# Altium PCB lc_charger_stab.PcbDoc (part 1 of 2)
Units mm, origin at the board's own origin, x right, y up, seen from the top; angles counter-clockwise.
Board outline 145 x 80 mm, 2 copper layers (Top Layer, Bottom Layer), stack 1.562 mm thick; 160 components, 79 nets, 423 pads, 71 vias.
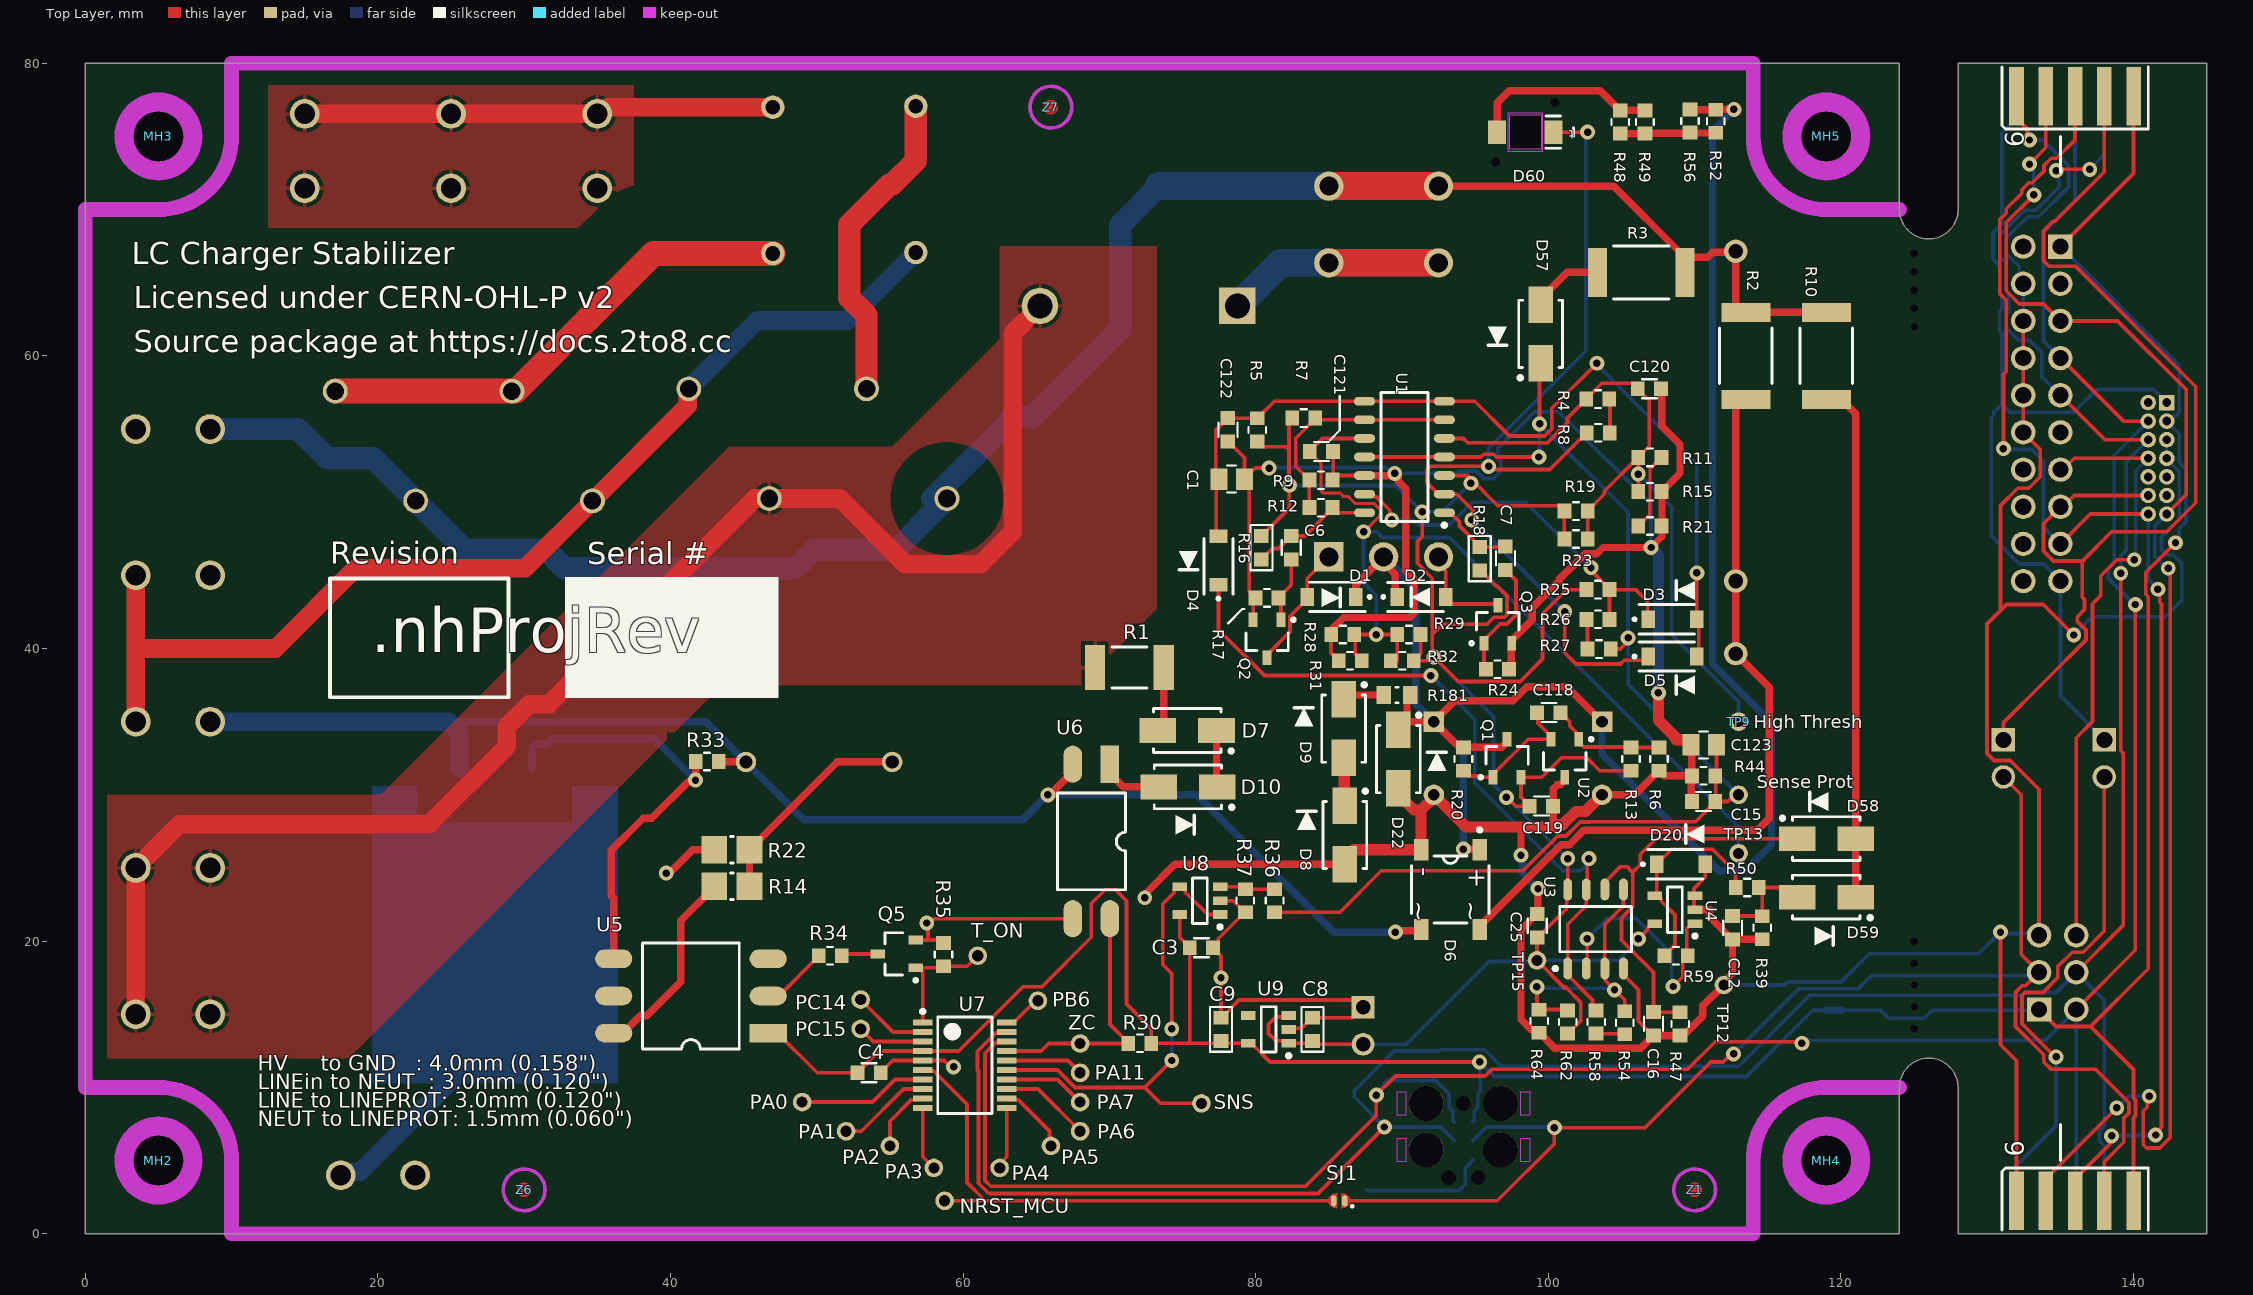
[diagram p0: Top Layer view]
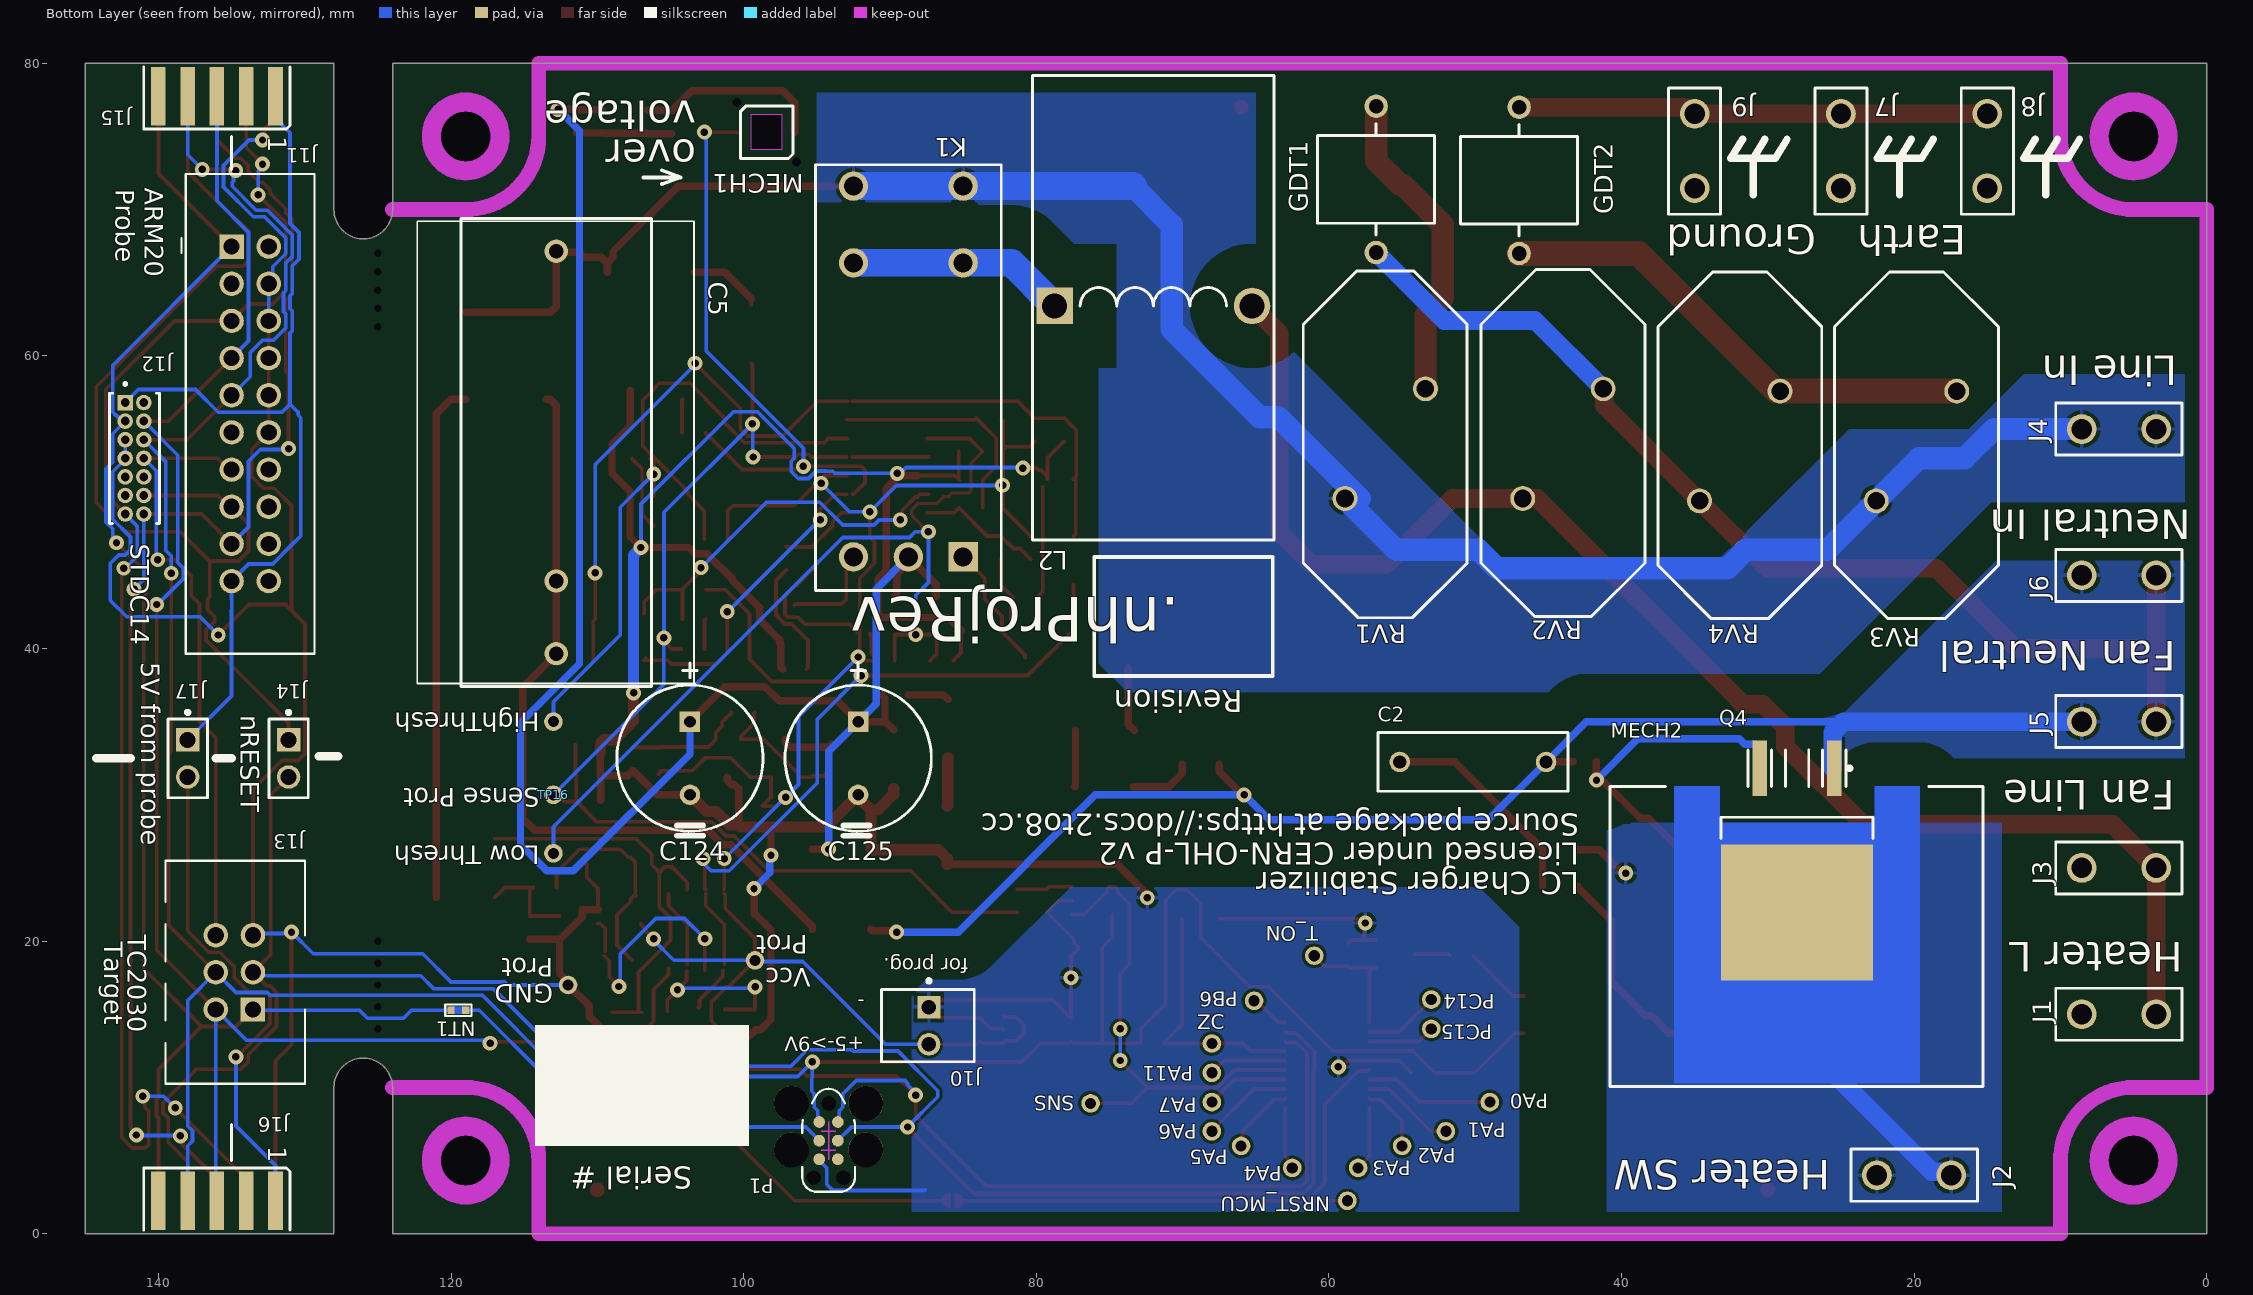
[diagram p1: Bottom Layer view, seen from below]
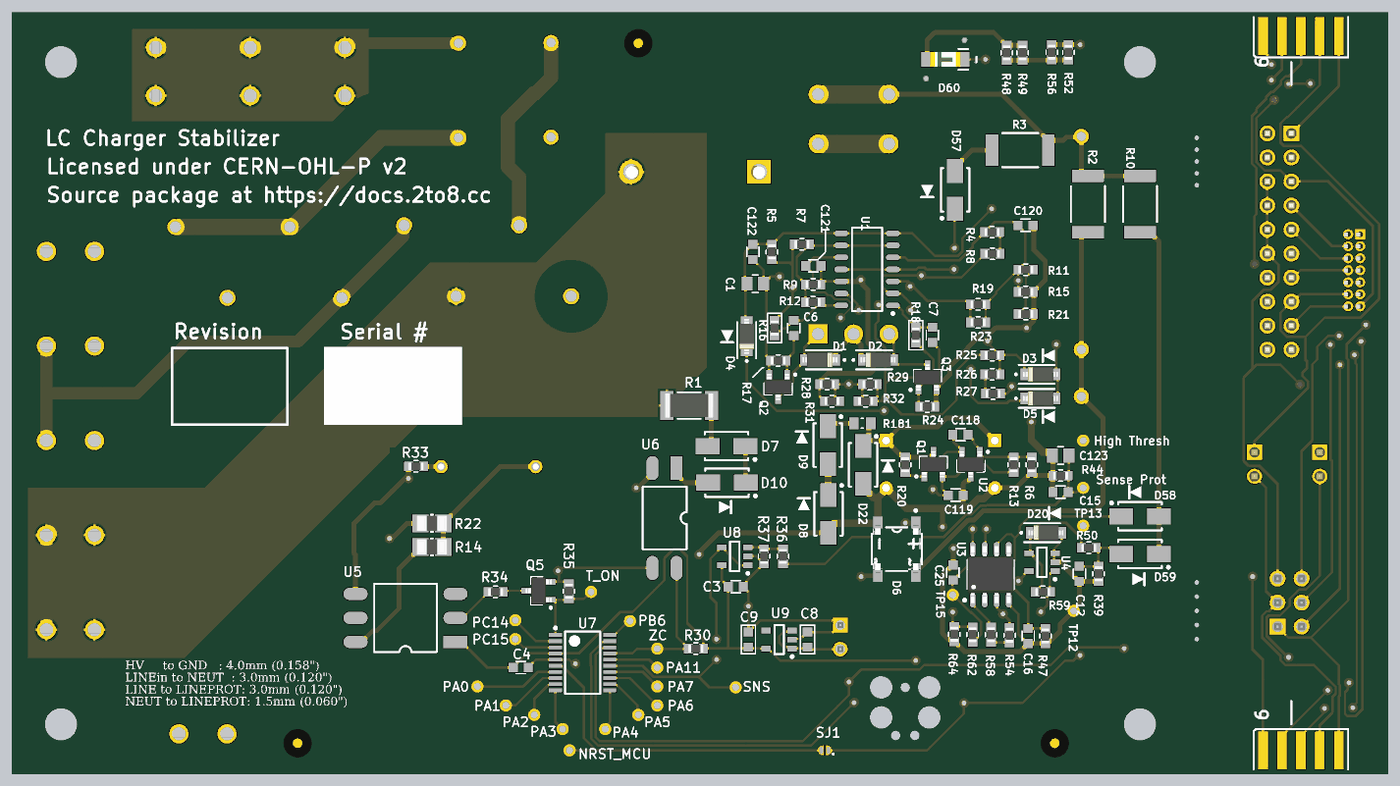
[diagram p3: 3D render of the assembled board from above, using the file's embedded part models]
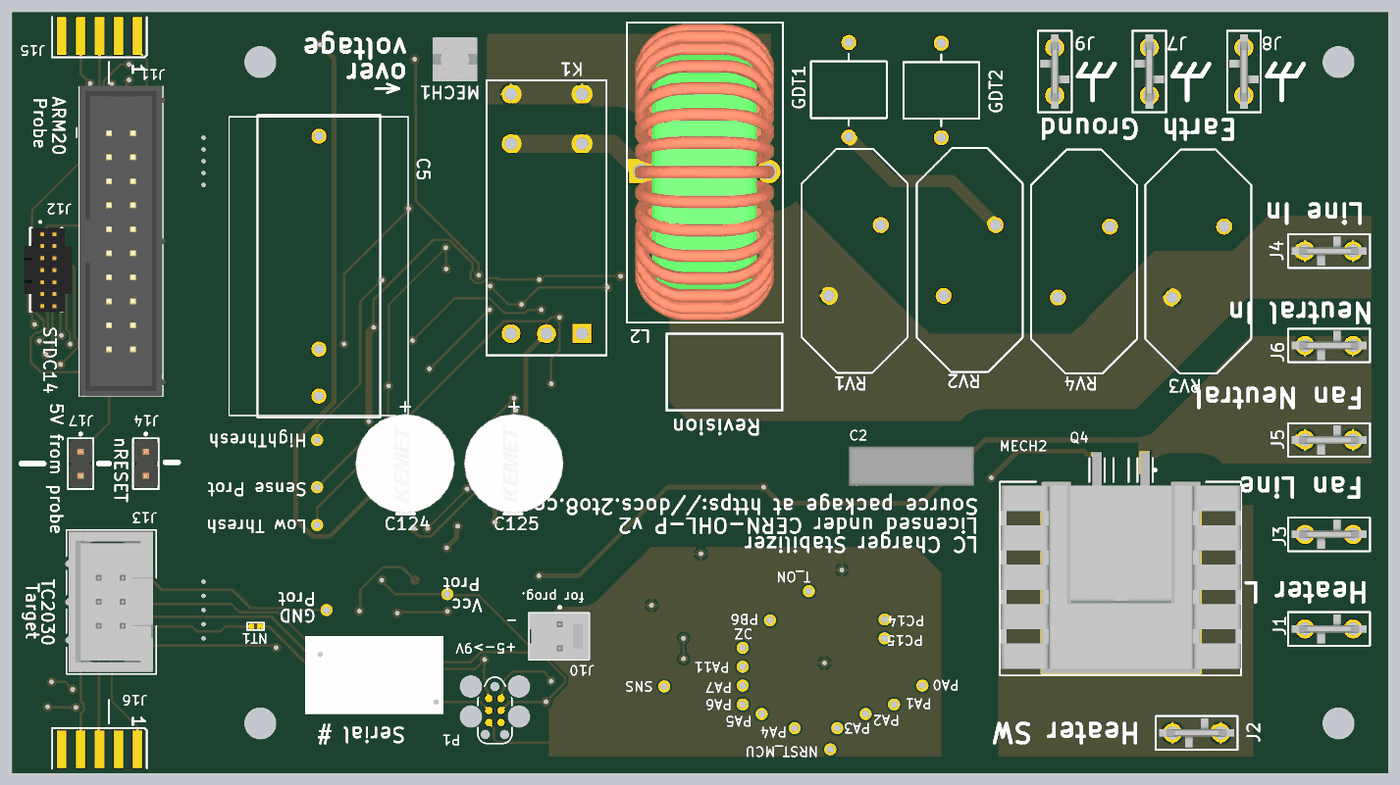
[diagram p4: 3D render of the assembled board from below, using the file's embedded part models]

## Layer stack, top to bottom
Top Solder: solder mask 0.0102, Solder Resist, Dk 3.5
Top Layer: signal copper 0.07
Dielectric 1: prepreg 1.4224, FR-4, Dk 4.5
Bottom Layer: signal copper 0.07
Bottom Solder: solder mask 0.0102, Solder Resist, Dk 3.5

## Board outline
0,0 0,80 124,80 124,70 ccw(c126,70) 128,70 128,80 145,80 145,0 128,0 128,10 ccw(c126,10) 124,10 124,0

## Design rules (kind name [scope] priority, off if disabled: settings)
AssemblyTestPointUsage [All] p1 off:
AssemblyTestpoint [All] p1 off: testpointundercomponent=TRUE minsize=1.016 maxsize=2.54 preferedsize=1.524 minholesize=0 maxholesize=1.016 preferedholesize=0.813 testpointgrid=0.025 usegrid=TRUE gridtolerance=0 allowsidetop=TRUE allowsidebottom=TRUE
Clearance Clearance_1_Line_SELV_FG [InNetClass('Line') vs InNetClass('SELV') or InNetClass('FG')] p1: gap=4 ignorepadtopadclearanceinfootprint=FALSE // REINFORCED for separated extremely low voltage
Clearance Clearance_2_LineProt_SELV_FG [InNetClass('LineProt') vs InNetClass('SELV') or InNetClass('FG')] p2: gap=4 ignorepadtopadclearanceinfootprint=FALSE // REINFORCED for separated extremely low voltage
Clearance Clearance_3_Neut_SELV_FG [InNetClass('Neut') vs InNetClass('SELV') or InNetClass('FG')] p3: gap=4 ignorepadtopadclearanceinfootprint=FALSE // REINFORCED for separated extremely low voltage
Clearance Clearance_4_Line_LineProt [InNetClass('Line') vs InNetClass('LineProt')] p4: gap=3 ignorepadtopadclearanceinfootprint=TRUE except(0: Arc-Hole Track-Hole SMDPad-Hole THPad-Hole Via-Hole Fill-Hole Poly-Hole Region-Hole Text-Hole) // FUNCTIONAL insulation for LN before relay (700Vrms/990VPeak)
Clearance Clearance_5_Neut_LineProt [InNetClass('Neut') vs InNetClass('LineProt')] p5: gap=1.5 ignorepadtopadclearanceinfootprint=TRUE except(0: Arc-Hole Track-Hole SMDPad-Hole THPad-Hole Via-Hole Fill-Hole Poly-Hole Region-Hole Text-Hole) // FUNCTIONAL insulation for 240VAC nominal
Clearance Clearance_6_Line_Neut [InNetClass('Line') vs InNetClass('Neut')] p6: gap=3 ignorepadtopadclearanceinfootprint=TRUE // more FUNCTIONAL insulation for 240VAC nominal
Clearance [All] p7: gap=0.2 ignorepadtopadclearanceinfootprint=TRUE except(0.25: Arc-Hole Track-Hole SMDPad-Hole THPad-Hole Via-Hole Fill-Hole Poly-Hole Region-Hole Text-Hole)
DiffPairsRouting [All] p1: maxlimit=0.254 minlimit=0.203 mostfreqgap=0.203 toplayer_minwidth=0.203 toplayer_maxwidth=0.368 toplayer_prefwidth=0.368 bottomlayer_minwidth=0.203 bottomlayer_maxwidth=0.368 bottomlayer_prefwidth=0.368 maxuncoupledlength=12.7
FabricationTestPointUsage [All] p1 off: valid=0 allowmultiple=FALSE
FabricationTestpoint [All] p1 off: side=3 testpointundercomponent=TRUE minsize=1.016 maxsize=2.54 preferedsize=1.524 minholesize=0 maxholesize=1.016 preferedholesize=0.813 testpointgrid=0.025 allowsidetop=TRUE allowsidebottom=TRUE usegrid=TRUE gridtolerance=0
Height [All] p1 off: minheight=0 maxheight=25.4 prefheight=12.7
HoleSize [All] p1: absolutevalues=TRUE maxlimit=5.08 minlimit=0.203 maxpercent=80.000 minpercent=20.000
MinimumAnnularRing [All] p1: minimumring=0.229
MinimumSolderMaskSliver [All] p1: minsoldermaskwidth=0.02
PolygonConnect [All] p1: connectstyle=Relief reliefconductorwidth=0.254 reliefentries=4 polygonreliefangle="90 Angle" airgapwidth=0.254
RoutingVias [All] p1: holewidth=0.508 width=1.016 viastyle="Through Hole" minholewidth=0.254 minwidth=0.711 maxholewidth=1.27 maxwidth=1.778
SMDNeckDown [All] p1: percent=90.000
SilkToSilkClearance [All] p1 off: silktosilkclearance=0.254
SilkToSolderMaskClearance [IsPad] p1: minsilkscreentomaskgap=0.127 clearancetoexposedcopper=TRUE
SolderMaskExpansion [All] p1: expansion=0.102 istentingtop=FALSE
SupplyNets "Schematic Supply Nets_4" [InNet('3V3')] p1: voltage=0.000
SupplyNets "Schematic Supply Nets_3" [InNet('GND')] p2: voltage=0.000
SupplyNets "Schematic Supply Nets_2" [InNet('GND_PROT')] p3: voltage=0.000
SupplyNets "Schematic Supply Nets_1" [InNet('Vcc_prot')] p4: voltage=0.000
SupplyNets "Schematic Supply Nets" [InNet('Vcoil')] p5: voltage=0.000
Width [All] p1: maxlimit=7.62 minlimit=0.178 preferedwidth=0.254
20 further rules are at their usual default settings.

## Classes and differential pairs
component class HeaterControl: C2 C3 C4 C8 C9 D7 D10 J1 J2 J9 J10 MECH2 NRST_MCU P1 PA0 PA1 PA2 PA3 PA4 PA5 PA6 PA7 PA11 PB6 PC14 PC15 Q4 Q5 R1 R14 R22 R30 R33 R34 R35 R36 R37 SJ1 SNS T_ON U5 U6 U7 U8 U9 ZC
component class DebugProbe: J11 J12 J13 J14 J15 J16 J17 NT1
net class FG: GND
component class Cover: MH2 MH3 MH4 MH5 Z1 Z6 Z7 Z15 Z16 Z17 Z18 Z19 Z20 Z21 Z22 Z23 Z24 Z25 Z26 Z27 Z28 Z29 Z30 Z31
net class Line: 3V3 ac_sense diffp GND_PROT heater_out input_ok LINE NC.MOV5 NetC2_1 NetC5_2 NetC6_2 NetC7_2 NetC118_1 NetC118_2 NetD8_K NetD9_K NetD20_K NetD57_A NetD58_A NetD60_A NetGDT1_2 NetQ5_3 NetR4_1 NetR7_2 NetR11_1 NetR14_1 NetR26_1 NetR48_1 NetR54_1 NRST NRST_MCU opto_k1 overvoltage# PA0 PA1 PA2 PA3 PA4 PA5 PA6 PA7 PA11 PB6 PC14 PC15 peak_neg peak_neg_inv peak_out peak_pos peak_thresh PROT_RESET PROT_SET ref_high ref_low reset sense_prot set SWDCLK SWDIO triac_on undervoltage# VCC_PROT VCOIL zero_cross
net class Neut: gate NetD7_A NetD7_K NetD10_A NEUT
net class LineProt: L2 LPROT
component class PowerHV: asdf GDT1 GDT2 J3 J4 J5 J6 J7 J8 K1 L2 RV1 RV2 RV3 RV4
component class Protect: C1 C5 C6 C7 C12 C15 C16 C25 C118 C119 C120 C121 C122 C123 C124 C125 D1 D2 D3 D4 D5 D6 D8 D9 D20 D22 D57 D58 D59 D60 MECH1 Q1 Q2 Q3 R2 R3 R4 R5 R6 R7 R8 R9 R10 R11 R12 R13 R15 R16 R17 R18 R19 R20 R21 R23 R24 R25 R26 R27 R28 R29 R31 R32 R39 R44 R47 R48 R49 R50 R52 R54 R56 R58 R59 R62 R64 R181 TP9 TP12 TP13 TP15 TP16 U1 U2 U3 U4

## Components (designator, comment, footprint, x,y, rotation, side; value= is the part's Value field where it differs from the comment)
C1 "CL21A226MOCLRNC" CAPC2012X135,0805, 78.354,51.577 r0 top value=22uF
C2 "R413F12200000M" CAP_RAD10P1304X09 50.155,32.245 r180 bottom value=2.2nF
C3 "CL10B104KB8NNNL" CAPC1608X09N,0603, 76.288,19.543 r0 top value=0.1u
C4 "CL10B104KB8NNNL" CAPC1608X09N,0603, 53.574,11 r0 top value=0.1u
C5 "R586R333050T0K" CAP_RAD28P3213X22 112.809,53.4 r270 bottom locked value=0.33uF
C6 "CL10B333KB8NNNC" CAPC1608X09N,0603, 82.421,46.892 r270 top value=33n
C7 "CL10B333KB8NNNC" CAPC1608X09N,0603, 97.065,46.168 r270 top value=33n
C8 "CL10B105KA8NFNC" CAPC1608X09N[0603] 83.876,13.962 r90 top value=1u
C9 "CL10B105KA8NFNC" CAPC1608X09N[0603] 77.626,13.962 r90 top value=1u
C12 "CL10B104KB8NNNL" CAPC1608X09N,0603, 112.588,20.913 r270 top value=0.1u
C15 "CL10B104KB8NNNL" CAPC1608X09N,0603, 110.605,29.543 r180 top value=0.1u
C16 "CL10B104KB8NNNL" CAPC1608X09N,0603, 107.186,14.347 r270 top value=0.1u
C25 "CL10B104KB8NNNL" CAPC1608X09N,0603, 99.247,21.053 r90 top value=0.1u
C118 "CL10B333KB8NNNC" CAPC1608X09N,0603, 100.034,35.62 r0 top value=33n
C119 "CL10A475KA8NQNC" CAPC1608X09N,0603, 99.525,29.225 r0 top value=4.7u
C120 "CL10B104KB8NNNL" CAPC1608X09N,0603, 106.911,57.749 r0 top value=0.1u
C121 "CL10B104KB8NNNL" CAPC1608X09N,0603, 84.493,53.462 r0 top value=0.1u
C122 "CL10A475KA8NQNC" CAPC1608X09N,0603, 78.099,54.945 r270 top value=4.7u
C123 "CL21A226MOCLRNC" CAPC2012X135,0805, 110.616,33.409 r180 top value=22uF
C124 "ESH477M035AH3AA" CAP_RAD5P_CYL_10X20 103.669,32.5 r90 bottom value=470uF
C125 "ESH477M035AH3AA" CAP_RAD5P_CYL_10X20 92.175,32.5 r90 bottom value=470uF
D1 "1N4148W-TP" SOD-123 85.187,43.526 r180 top
D2 "1N4148W-TP" SOD-123 91.32,43.525 r0 top
D3 "1N4148W-TP" SOD-123 108.491,41.994 r0 top
D4 "1N4148W-TP" SOD-123 77.454,46.008 r90 top
D5 "1N4148W-TP" SOD-123 108.491,39.454 r0 top
D6 "ABS10" SOP400P640X170-4N_BRIDGE 93.304,23.524 r270 top
D7 "SMAZ10-13-F" DO-214AC 75.316,34.4 r180 top value=10V
D8 "SMAZ8V2-13-F" DO-214AC 86.087,27.252 r270 top value=8.2V
D9 "SMAZ8V2-13-F" DO-214AC 86.013,34.524 r270 top value=8.2V
D10 "SMAZ10-13-F" DO-214AC 75.365,30.545 r180 top value=10V
D20 "MBR130T1G" SOD-123 109.065,25.253 r0 top
D22 "SMAJ24A-13-F" DO-214AC 89.743,32.44 r270 top
D57 "S1V" DO-214AC 99.477,61.5 r90 top
D58 "S1V" DO-214AC 119,27 r0 top
D59 "S1V" DO-214AC 119,23 r180 top
D60 "APTR3216SURCK" LEDC3216X08NREDBOT,1206, 98.429,75.292 r180 top
GDT1 "CG31.0L" LITTELFUSE_CG3x 56.772,72.067 r90 bottom
GDT2 "CG32.5L" LITTELFUSE_CG3x 47,72 r90 bottom
J1 "TE_63849-1" AMP_63849-1 6,15 r180 bottom
J2 "TE_63849-1" AMP_63849-1 20,4 r0 bottom
J3 "TE_63849-1" AMP_63849-1 6,25 r180 bottom
J4 "TE_63849-1" AMP_63849-1 6,55 r180 bottom
J5 "TE_63849-1" AMP_63849-1 6,35 r180 bottom
J6 "TE_63849-1" AMP_63849-1 6,45 r180 bottom
J7 "TE_63849-1" AMP_63849-1 25,74 r270 bottom
J8 "TE_63849-1" AMP_63849-1 15,74 r270 bottom
J9 "TE_63849-1" AMP_63849-1 35,74 r270 bottom
J10 "22-23-2021" MOLX-22-23-2021_V 87.337,14.219 r270 bottom
J11 "SBH11-PBPC-D10-ST-BK" SULLINS_SBH11-PBPC-D10-ST-BK 133.73,56.038 r270 bottom
J12 "FTSH-107-01-S-D-K" SAMTEC_FTSH-107-01-x-D-K 141.635,53 r270 bottom
J13 "75869-131LF" AMPHENOL_75869-131LF 134.808,17.868 r90 bottom
J14 "61300211121" 61300211121 131.104,32.489 r270 bottom
J15 "AVX_009159010_ARROW" AVX_009159010_ARROW_NOSLOT 136,80 r270 bottom
J16 "AVX_009159010_NO_ARROW" AVX_009159010_NO_ARROW_NOSLOT 136,0 r270 bottom
J17 "61300211121" 61300211121 138,32.489 r270 bottom
K1 "TE_CONN_2-1415898-5" TE_RT1_2COIL_LATCHING 88.743,58.512 r0 bottom
L2 "BELFUSE_HCTI-47-10.7" BELFUSE_HCTI_TOROIDAL_INDUCTOR 72,63.414 r90 bottom value=47uH
MECH1 "VLP-400-F" BIVAR_VLP-400-F 98.429,75.292 r270 bottom
MECH2 "V-1102-SMD/A-L" ASSMANN_V-1102-SMD/A 28,21.675 r0 bottom
MH2 "MOUNTING_HOLE_3MM_UNPLATED" MOUNT_HOLE_3MM_NOCOPPER 5,5 r90 top
MH3 "MOUNTING_HOLE_3MM_UNPLATED" MOUNT_HOLE_3MM_NOCOPPER 5,75 r90 top
MH4 "MOUNTING_HOLE_3MM_UNPLATED" MOUNT_HOLE_3MM_NOCOPPER 119,5 r90 top
MH5 "MOUNTING_HOLE_3MM_UNPLATED" MOUNT_HOLE_3MM_NOCOPPER 119,75 r90 top
NRST_MCU "Test Point 30mil plated" TP_TH078H127P 58.739,2.25 r90 top
NT1 "NET_TIE" NETTIE_0.508mm_NOPADS 119.5,15.275 r180 bottom net-tie
P1 "TC2030" TAG-TC2030-LEGS 94.196,6.365 r270 bottom
PA0 "Test Point 30mil plated" TP_TH078H127P 49,9 r90 top
PA1 "Test Point 30mil plated" TP_TH078H127P 52,7 r90 top
PA2 "Test Point 30mil plated" TP_TH078H127P 55,6 r90 top
PA3 "Test Point 30mil plated" TP_TH078H127P 58,4.5 r90 top
PA4 "Test Point 30mil plated" TP_TH078H127P 62.5,4.5 r90 top
PA5 "Test Point 30mil plated" TP_TH078H127P 66,6 r90 top
PA6 "Test Point 30mil plated" TP_TH078H127P 68,7 r90 top
PA7 "Test Point 30mil plated" TP_TH078H127P 68,9 r90 top
PA11 "Test Point 30mil plated" TP_TH078H127P 68,11 r90 top
PB6 "Test Point 30mil plated" TP_TH078H127P 65.114,15.92 r90 top
PC14 "Test Point 30mil plated" TP_TH078H127P 53,16 r90 top
PC15 "Test Point 30mil plated" TP_TH078H127P 53,14 r90 top
Q1 "BCV72,215" SOT95P275X125-3N 97.175,32.5 r90 top
Q2 "IRLML6346TRPBF" SOT95P275X125-3N 80.772,40.663 r270 top
Q3 "IRLML6346TRPBF" SOT95P275X125-3N 96.551,41.661 r90 top
Q4 "ACST1210-7G" TO-263_TRIAC_N 28,25.515 r270 bottom
Q5 "IRLML6346TRPBF" SOT95P275X125-3N 55.454,19.122 r180 top
R1 "CHV2010-FX-2203ELF" RESC5025X60,2010, 71.365,38.703 r0 top value=220kR
R2 "CHV2512-FX-1004ELF" RESC6534X70,2512, 113.5,60 r270 top value=1M
R3 "CHV2512-FX-1004ELF" RESC6534X70,2512, 106.35,65.697 r180 top value=1M
R4 "ERJ-3EKF4753V" RESC1608X05AN,0603, 103.379,57.044 r180 top value=475k
R5 "ERJ-3EKF1004V" RESC1608X05AN,0603, 80.105,54.945 r90 top value=1M
R6 "ERA-3AEB4221V" RESC1608X05AN,0603, 107.559,32.44 r270 top value=4.22k
R7 "ERJ-3EKF1003V" RESC1608X05AN,0603, 83.281,55.745 r0 top value=100k
R8 "ERJ-3EKF1004V" RESC1608X05AN,0603, 103.411,54.742 r180 top value=1M
R9 "ERJ-3EKF1003V" RESC1608X05AN,0603, 84.465,51.504 r0 top value=100k
R10 "CHV2512-FX-1004ELF" RESC6534X70,2512, 119,60 r270 top value=1M
R11 "ERA-3AEB1742V" RESC1608X05AN,0603, 106.936,53.062 r180 top value=17.4k
R12 "ERJ-3EKF1004V" RESC1608X05AN,0603, 84.465,49.624 r0 top value=1M
R13 "ERA-3AEB2742V" RESC1608X05AN,0603, 105.652,32.44 r90 top value=27.4k
R14 "ERJ-P08J510V" RESC3216X70,1206, 44.19,23.75 r0 top value=51R
R15 "RMCF0603FT140K" RESC1608X05AN,0603, 106.936,50.719 r0 top value=140k
R16 "RMCF0603FT10K0" RESC1608X05AN[0603] 80.389,46.892 r270 top value=10k
R17 "ERJ-3EKF4753V" RESC1608X05AN,0603, 80.772,43.457 r0 top value=475k
R18 "RMCF0603FT10K0" RESC1608X05AN[0603] 95.313,46.143 r90 top value=10k
R19 "ERA-3AEB2742V" RESC1608X05AN,0603, 101.898,49.391 r0 top value=27.4k
R20 "RMCF0603FT2K74" RESC1608X05AN,0603, 94.196,32.44 r90 top value=2.74k
R21 "ERJ-3EKF2210V" RESC1608X05AN,0603, 106.936,48.376 r0 top value=221
R22 "ERJ-P08J151V" RESC3216X70,1206, 44.19,26.25 r180 top value=150R
R23 "ERJ-3EKF1004V" RESC1608X05AN,0603, 101.898,47.486 r0 top value=1M
R24 "ERJ-3EKF4753V" RESC1608X05AN,0603, 96.525,38.579 r180 top value=475k
R25 "ERA-3AEB2742V" RESC1608X05AN,0603, 103.397,44.025 r180 top value=27.4k
R26 "ERJ-3EKF1004V" RESC1608X05AN,0603, 103.397,41.993 r0 top value=1M
R27 "ERJ-3EKF1004V" RESC1608X05AN,0603, 103.473,39.961 r180 top value=1M
R28 "ERJ-3EKF3322V" RESC1608X05AN,0603, 85.949,40.954 r180 top value=33.2k
R29 "ERJ-3EKF1003V" RESC1608X05AN,0603, 90.47,40.954 r180 top value=100k
R30 "ERJ-3EKF1003V" RESC1608X05AN,0603, 72.075,13.012 r180 top value=100k
R31 "ERA-3AEB622V" RESC1608X05AN,0603, 86.457,39.164 r180 top value=6.2k
R32 "ERA-3AEB2742V" RESC1608X05AN,0603, 90.013,39.164 r180 top value=27.4k
R33 "ERJ-3EKF3920V" RESC1608X05AN,0603, 42.509,32.277 r0 top value=392R
R34 "ERJ-3EKF3920V" RESC1608X05AN,0603, 50.915,19 r0 top value=392R
R35 "ERJ-3EKF1003V" RESC1608X05AN,0603, 58.657,19.077 r90 top value=100k
R36 "RT0603BRD071ML" RESC1608X05AN,0603, 81.288,22.762 r90 top value=1MR
R37 "RT0603BRD071ML" RESC1608X05AN,0603, 79.288,22.762 r270 top value=1MR
R39 "ERA-3AEB4221V" RESC1608X05AN,0603, 114.62,20.913 r270 top value=4.22k
R44 "ERA-3AEB2742V" RESC1608X05AN,0603, 110.616,31.295 r180 top value=27.4k
R47 "ERA-3AEB4221V" RESC1608X05AN,0603, 109.008,14.341 r270 top value=4.22k
R48 "ERJ-3EKF1001V" RESC1608X05AN,0603, 104.915,75.989 r90 top value=1k
R49 "ERJ-3EKF1001V" RESC1608X05AN,0603, 106.6,75.989 r90 top value=1k
R50 "ERJ-3EKF1003V" RESC1608X05AN,0603, 113.595,23.669 r180 top value=100k
R52 "ERJ-3EKF1001V" RESC1608X05AN,0603, 111.443,76.035 r270 top value=1k
R54 "ERJ-3EKF4753V" RESC1608X05AN,0603, 105.221,14.419 r90 top value=475k
R56 "ERJ-3EKF1001V" RESC1608X05AN,0603, 109.679,76.05 r270 top value=1k
R58 "ERJ-3EKF1004V" RESC1608X05AN,0603, 103.267,14.475 r90 top value=1M
R59 "ERJ-3EKF1003V" RESC1608X05AN,0603, 108.735,19 r0 top value=100k
R62 "ERA-3AEB2742V" RESC1608X05AN,0603, 101.323,14.475 r90 top value=27.4k
R64 "ERA-3AEB622V" RESC1608X05AN,0603, 99.374,14.526 r270 top value=6.2k
R181 "ERJ-P06F1000V" RESC2012X06N,0805, 89.66,36.821 r180 top value=100
RV1 "TMOV20RP300E" MOV_RAD7.5P5.5S_DISC_20X11.5 56.15,54 r270 bottom
RV2 "TMOV20RP300E" MOV_RAD7.5P5.5S_DISC_20X11.5 44,54 r90 bottom
RV3 "TMOV20RP300E" MOV_RAD7.5P5.5S_DISC_20X11.5 19.837,53.838 r90 bottom
RV4 "TMOV20RP300E" MOV_RAD7.5P5.5S_DISC_20X11.5 31.914,53.838 r90 bottom
SJ1 "SOLDER_JUMPER_OPEN" SOLDER_JUMPER_OPEN 85.706,2.25 r180 top
SNS "Test Point 30mil plated" TP_TH078H127P 76.288,8.909 r90 top
T_ON "Test Point 30mil plated" TP_TH078H127P 61,19 r90 top
TP9 "TP TH  0.78mm" TP_TH078H127P 113,35 r270 top
TP12 "TP TH  0.78mm" TP_TH078H127P 112,17 r270 top
TP13 "TP TH  0.78mm" TP_TH078H127P 113,26 r270 top
TP15 "TP TH  0.78mm" TP_TH078H127P 99.222,18.686 r0 top
TP16 "TP TH  0.78mm" TP_TH078H127P 113,30 r270 bottom
U1 "LP2901DR" SOIC127P600X175-14N 90.165,53.09 r180 top
U2 "TS3431CILT" SOT95P275X125-3N 101.125,32.5 r270 top
U3 "TS393IDT" SOIC127P600X175-8N 103.228,20.824 r90 top
U4 "TLV2401IDBVR" SOT95P280X145-5N 108.651,22.144 r180 top
U5 "EL3063S1(TA)-V" DIP6_SMD_8MM 41.4,16.25 r180 top
U6 "LTV-814S-TA1" DIP4_SMD_8MM 68.765,26.81 r270 top
U7 "STM32C011F6P6TR" TSOP65P640X120-20N 60.114,11.515 r0 top
U8 "TLV2401IDBVR" SOT95P280X145-5N 76.188,22.762 r180 top
U9 "LDK320AM33R" SOT95P280X145-5N 80.876,13.962 r180 top
Z1 "FIDUCIAL_1_3" FIDUCIAL_1_3_KEEPOUT 110,3 r90 top
Z6 "FIDUCIAL_1_3" FIDUCIAL_1_3_KEEPOUT 30,3 r0 top
Z7 "FIDUCIAL_1_3" FIDUCIAL_1_3_KEEPOUT 66,77 r0 top
ZC "Test Point 30mil plated" TP_TH078H127P 68,13 r90 top

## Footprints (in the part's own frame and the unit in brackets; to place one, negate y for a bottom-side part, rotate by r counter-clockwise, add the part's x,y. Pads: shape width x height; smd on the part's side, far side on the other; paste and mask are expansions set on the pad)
61300211121 [mm] "Pin Header, pitch 2.54 mm, THT, Vertical, single row, 2p"
  rect 1.6x1.6 hole 1.1: 1(-1.27,0)
  round 1.6 hole 1.1: 2(1.27,0)
  silkscreen extent -3.26,-1.35 2.69,1.35, body extent -2.54,-1.27 2.54,1.27, height 8.57
AMP_63849-1 [mil] "PCB-mount 0.250\" (or 0.187\") wide quick connect terminal, male vertical"
  round 80 hole 55: 1(-100,0) 2(100,0)
  silkscreen extent -170,-70 170,70, body extent -156,-61 156,61, height 409
AMPHENOL_75869-131LF [mm] "2x3 0.100\" pitch through-hole vertical header shrouded"
  rect 1.67x1.67 / inner round 1.67 / far side rect 1.67x1.67 hole 1.11: 1(-2.54,-1.27)
  round 1.67 hole 1.11: 2(-2.54,1.27) 3(0,-1.27) 4(0,1.27) 5(2.54,-1.27) 6(2.54,1.27)
  silkscreen extent -7.62,-4.83 7.62,4.7, body extent -7.41,-4.44 7.42,4.83, height 9.33
ASSMANN_V-1102-SMD/A [mil] "SMT heatsink for TO-263 (D2PAK) packages"
  rect 63x44 smd paste+0 mask+0: 1(0,0)
  Top Layer region: -330.71,-350.39 -330.71,448.82 330.71,448.82 330.71,-350.39 208.66,-350.39 208.66,-251.97 -208.66,-251.97 -208.66,-350.39
  silkscreen extent -500,-449 504,457, body extent -500,-334 500,429, height 454
AVX_009159010_ARROW_NOSLOT [mm] "Footprint for AVX 10-pin PCB edige connector without a slot, the side that connects to the arrow on the connector."
  rect 4x1 smd paste-2539.97: 1(2.25,4) 2(2.25,2) 3(2.25,0) 4(2.25,-2) 5(2.25,-4)
  rect 4x1 smd far side paste-2539.97: 6(2.25,4) 7(2.25,2) 8(2.25,0) 9(2.25,-2) 10(2.25,-4)
  silkscreen extent 0.25,-5 4.5,5
AVX_009159010_NO_ARROW_NOSLOT [mm] "Footprint for AVX 10-pin PCB edige connector without a slot, the side that doesn't have the arrow on the connector."
  rect 4x1 smd paste-2539.97: 1(-2.25,4) 2(-2.25,2) 3(-2.25,0) 4(-2.25,-2) 5(-2.25,-4)
  rect 4x1 smd far side paste-2539.97: 6(-2.25,4) 7(-2.25,2) 8(-2.25,0) 9(-2.25,-2) 10(-2.25,-4)
  silkscreen extent -4.5,-5 -0.25,5
BELFUSE_HCTI_TOROIDAL_INDUCTOR [mm] "BelFuse HCTI series high-current toroidal inductor.  13.5 mm pitch, 33 mm diameter vertical toroid"
  rect 2.5x2.5 hole 1.7: 1(0,6.75)
  round 2.5 hole 1.7: 2(0,-6.75)
  silkscreen extent -16,-8.25 15.75,8.25, body extent -15.75,-7.37 15.61,7.44, height 31.41
BIVAR_VLP-400-F [mm] "Light Pipe Single Clear Rigid Board Mount, Press Fit"
  round 0.3 hole 0.61 unplated: 1(2.032,2.032) 2(-2.032,-2.032)
  silkscreen extent -1.8,-1.8 1.8,1.8, body extent -2.35,-2.35 2.35,2.35, height 10.16
CAP_RAD5P_CYL_10X20 [mm] "Radial electrolytic 5 mm pitch 10 mm dia, 20 mm high with + and - terminals."
  rect 1.4x1.4 hole 0.8: +(2.5,0)
  round 1.4 hole 0.8: -(-2.5,0)
  silkscreen extent -5,-5 6.5,5, body extent -5.25,-5.22 5.25,5.28, height 22
CAP_RAD10P1304X09 [mm] "Box capacitor 10 mm pin pitch, 13 mm length, 4 mm width, 9 mm height"
  round 1.4 hole 0.9: 1(-5,0) 2(5,0)
  silkscreen extent -6.5,-2 6.5,2, body extent -6.65,-2.11 6.65,2.1, height 9.1
CAP_RAD28P3213X22 [mm] "Box capacitor 27.5 mm pin pitch, 31.5 mm length, 13 mm width, 22 mm height"
  round 1.6 hole 1: 1(-13.75,0) 2(13.75,0)
  silkscreen extent -16,-6.5 16,6.5, body extent -16,-6.5 16,6.5, height 22
CAPC1608X09N,0603, [mm] "Chip Capacitor, Body 1.6x0.8mm, IPC Medium Density, 0603 imperial with minimal silk"
  rect 0.95x1 smd: 1(-0.8,0) 2(0.8,0)
  silkscreen extent -0.5,-0.64 0.5,0.65, body extent -0.85,-0.45 0.85,0.45, height 0.9
CAPC1608X09N[0603] [mm] "Chip Capacitor, Body 1.6x0.8mm, IPC Medium Density, 0603 imperial with silk box"
  rect 0.95x1 smd: 1(-0.8,0) 2(0.8,0)
  silkscreen extent -1.53,-0.75 1.53,0.75, body extent -0.85,-0.45 0.85,0.45, height 0.9
CAPC2012X135,0805, [mm] "Chip Capacitor, Body 2.0x1.2mm, IPC Medium Density, Height 1.35 mm, 0805 imperial with minimal silk"
  rect 1.16x1.47 smd: 1(-0.875,0) 2(0.875,0)
  silkscreen extent -0.3,-0.92 0.3,0.92, body extent -1,-0.63 1,0.63, height 1.35
DIP4_SMD_8MM [mm] "DIP package size, but SMD version, 8mm between pads"
  rect 2.54x1.27 smd: 1(-5.28,1.27)
  oval 2.54x1.27 smd: 2(-5.28,-1.27) 3(5.28,-1.27) 4(5.28,1.27)
  silkscreen extent -3.3,-2.3 3.3,2.34, body extent -3.3,-2.3 3.3,2.3, height 3.9
DIP6_SMD_8MM [mm] "DIP package size, but SMD version, 8mm between pads"
  rect 2.54x1.27 smd: 1(-5.28,2.54)
  oval 2.54x1.27 smd: 2(-5.28,0) 3(-5.28,-2.54) 4(5.28,-2.54) 5(5.28,0) 6(5.28,2.54)
  silkscreen extent -3.3,-3.61 3.3,3.61, body extent -3.3,-3.6 3.3,3.57, height 3.9
DO-214AC [mm] "SMA Molded Diode, 2-Leads, Body 4.30x2.61mm, IPC Medium Density with A and K pads"
  rect 2.5x1.7 smd: A(2,0) K(-2,0)
  silkscreen extent -3.13,-1.5 2.3,1.52, body extent -2.3,-1.46 2.3,1.46, height 2.4
FIDUCIAL_1_3_KEEPOUT [mm] "1mm dia fiducial with 3mm dia keepout"
  Top Layer circle w0.5: c0,0 r0.25
  Top Layer keep-out circle w0.254: c0,0 r1.425
LEDC3216X08NREDBOT,1206, [mm] "Chip LED Body 3.2x1.6mm, IPC Medium Density, red, board cutout for bottom projection"
  rect 1.237x1.6 smd: A(1.932,0) K(-1.932,0)
  Top Layer keep-out region: 1.2,-1.3 1.2,1.3 -1.2,1.3 -1.2,-1.3
  Keep-Out Layer board cut-out: -1.075,1.175 1.075,1.175 1.075,-1.175 -1.075,-1.175
  silkscreen extent -3.3,-1.1 -1.4,1.1, body extent -1.6,-0.8 1.6,0.8, height 0.26
LITTELFUSE_CG3x [mm] "for gas discharge tubes and other wide axial components"
  round 1.6 hole 1: 1(-5,0) 2(5,0)
  silkscreen extent -3.8,-4 3.8,4, body extent -5.4,-4 5.4,4, height 8
MOLX-22-23-2021_V [mm] "THD, 2-Leads, Body 6.35x4.93mm, Pitch 2.54mm"
  rect 1.55x1.55 hole 1: 1(-1.27,0)
  round 1.55 hole 1: 2(1.27,0)
  silkscreen extent -3.19,-3.25 2.46,3.1, body extent -2.46,-3.25 2.46,3.1, height 10.66
MOUNT_HOLE_3MM_NOCOPPER [mm] "Mounting hole for M3 screw, unplated"
  round 1 hole 3.4 unplated: 1(0,0)
  Keep-Out Layer circle w1.3: c0,0 r2.35
MOV_RAD7.5P5.5S_DISC_20X11.5 [mm] "MOV radial disc, 7.5 mm pitch with 5.5 mm offset, 20 mm dia. 11.5 mm thick, max height 26 mm."
  round 1.7 hole 1.2: 1(-3.75,2.75) 2(3.75,-2.75)
  silkscreen extent -11.8,-5.6 11.9,5.6, body extent -12,-5.75 12,5.75, height 28
NETTIE_0.508mm_NOPADS [mm] "Net tie that is just a 0.508mm wide trace with no pads"
  rect 0.5x0.508 smd paste-0.508: 1(-0.5,0) 2(0.5,0)
  Top Layer lines w0.508: 0.5,0 -0.5,0
  silkscreen extent -0.9,-0.4 0.9,0.4
RESC1608X05AN,0603, [mm] "Chip Resistor, Body 1.6x0.8mm, IPC Medium Density, 0603 imperial with minimal silk"
  rect 0.94x1.02 smd: 1(-0.79,0) 2(0.79,0)
  silkscreen extent -0.2,-0.6 0.2,0.6, body extent -0.8,-0.4 0.8,0.4, height 0.55
RESC1608X05AN[0603] [mm] "Chip Resistor, Body 1.6x0.8mm, IPC Medium Density, 0603 imperial with silk box"
  rect 0.95x1 smd: 1(-0.8,0) 2(0.8,0)
  silkscreen extent -1.55,-0.75 1.55,0.75, body extent -0.8,-0.4 0.8,0.4, height 0.55
RESC2012X06N,0805, [mm] "Chip Resistor, 2-Leads, Body 2.00x1.20mm, IPC Medium Density, 0805 imperial, minimal silk"
  rect 1x1.25 smd: 1(-0.9,0) 2(0.9,0)
  silkscreen extent -0.1,-0.53 0.1,0.53, body extent -1.05,-0.63 1.05,0.63, height 0.6
RESC3216X70,1206, [mm] "Chip Resistor, 2-Leads, Body 3.2x1.6mm, IPC Medium Density, 1206 imperial, minimal silk"
  rect 1.75x1.87 smd: 1(-1.21,0) 2(1.21,0)
  silkscreen extent -0.1,-0.9 0.1,0.9, body extent -1.6,-0.8 1.6,0.8, height 0.89
RESC5025X60,2010, [mil] "Chip Resistor, 2-Leads, Body 5.0x2.5mm, IPC Medium Density, Height 0.6 mm, 2010 imperial, minimal silk"
  rect 55x120 smd: 1(-92.52,0) 2(92.52,0)
  silkscreen extent -47,-55 47,55, body extent -101,-52 101,52, height 28
RESC6534X70,2512, [mm] "Chip Resistor, 2-Leads, Body 6.5x3.4mm, IPC Medium Density, Height 0.75 mm, 2512 imperial, minimal silk"
  rect 1.3x3.35 smd: 1(-2.975,0) 2(2.975,0)
  silkscreen extent -1.9,-1.8 1.9,1.8, body extent -3.25,-1.65 3.25,1.65, height 0.7
SAMTEC_FTSH-107-01-x-D-K [mm] "14-pin (2x7) 0.050\" pitch through-hole header with keying shroud"
  rect 1.06x1.06 hole 0.6 mask+0.08: 1(-3.81,-0.635)
  round 1.06 hole 0.6 mask+0.08: 2(-3.81,0.635) 3(-2.54,-0.635) 4(-2.54,0.635) 5(-1.27,-0.635) 6(-1.27,0.635) 7(0,-0.635) 8(0,0.635) 9(1.27,-0.635) 10(1.27,0.635) 11(2.54,-0.635) 12(2.54,0.635) 13(3.81,-0.635) 14(3.81,0.635)
  silkscreen extent -5.18,-1.72 4.44,1.72, body extent -4.42,-2.32 4.47,2.76, height 5.76
SOD-123 [mil] "SOD-123 SMD diode with A and K pads"
  rect 36x48 smd: A(65.35,0) K(-65.35,0)
  silkscreen extent -106,-39 59,39, body extent -73,-31 73,32, height 53
SOIC127P600X175-8N [mm] "SOIC, 8-Leads, Body 4.90x3.90mm, Pitch 1.27mm, IPC Medium Density, SO-8"
  oval 1.5x0.6 smd: 1(-2.7,1.905) 2(-2.7,0.635) 3(-2.7,-0.635) 4(-2.7,-1.905) 5(2.7,-1.905) 6(2.7,-0.635) 7(2.7,0.635) 8(2.7,1.905)
  silkscreen extent -2.82,-2.45 1.55,2.88, body extent -3,-2.45 3,2.45, height 1.75
SOIC127P600X175-14N [mm] "SOIC, 14-Leads, Body 8.65x3.90mm, Pitch 1.27mm, IPC Medium Density, SO-14"
  oval 1.45x0.6 smd: 1(-2.725,3.81) 2(-2.725,2.54) 3(-2.725,1.27) 4(-2.725,0) 5(-2.725,-1.27) 6(-2.725,-2.54) 7(-2.725,-3.81) 8(2.725,-3.81) 9(2.725,-2.54) 10(2.725,-1.27) 11(2.725,0) 12(2.725,1.27) 13(2.725,2.54) 14(2.725,3.81)
  silkscreen extent -2.85,-4.4 1.6,4.78, body extent -2,-4.4 2,4.4, height 1.75
SOLDER_JUMPER_OPEN [mil] "Solder paste closed jumper"
  oval 15x30 smd mask+0: 1(-15,0) 2(15,0)
  Top Layer region: -30.08,0.01 -28.82,6.33 -23.82,13.82 -16.33,18.82 -7.5,20.58 -4.99,20.08 -5,20 -4.99,-20.08 -7.5,-20.58 -16.33,-18.82 -23.82,-13.82 -28.82,-6.33 -30.08,-0.01
  Top Layer region: 4.99,-20.08 7.5,-20.58 16.33,-18.82 23.82,-13.82 28.82,-6.33 30.08,-0.01 30,0 30.08,0.01 28.82,6.33 23.82,13.82 16.33,18.82 7.5,20.58 4.99,20.08 5,20
  silkscreen extent -36,14 -34,16
SOP400P640X170-4N_BRIDGE [mm] "Bridge Rectifier SOPA-4, SOP, 4-Leads, Body 5.05x4.40mm, Pitch 4.00mm, IPC Medium Density"
  rect 1.45x1 smd paste+0 mask+0: +(-2.725,2) -(-2.725,-2) AC1(2.725,2) AC2(2.725,-2)
  silkscreen extent -4.2,-2.65 2.3,2.65, body extent -3.55,-2.75 3.55,2.75, height 0.25
SOT95P275X125-3N [mm] "SOT23, 3-Leads, Body 2.90x2.75mm, Pitch 0.95mm, IPC Medium Density"
  rect 1x0.6 smd: 1(-1.3,0.95) 2(-1.3,-0.95) 3(1.3,0)
  silkscreen extent -1.42,-1.45 0.8,1.92, body extent -1.38,-1.45 1.38,1.45, height 1.25
SOT95P280X145-5N [mm] "SOT23, 5-Leads, Body 2.90x2.80mm, Pitch 0.95mm, IPC Medium Density"
  rect 1x0.6 smd: 1(-1.375,0.95) 2(-1.375,0) 3(-1.375,-0.95) 4(1.375,-0.95) 5(1.375,0.95)
  silkscreen extent -1.5,-1.55 0.5,1.92, body extent -0.88,-1.52 0.87,1.53, height 1.45
SULLINS_SBH11-PBPC-D10-ST-BK [mm] "2x10 0.100\" (2.54 mm) vertical header, shrouded"
  rect 1.67x1.67 / inner round 1.67 / far side rect 1.67x1.67 hole 1.11: 1(-11.43,-1.27)
  round 1.67 hole 1.11: 2(-11.43,1.27) 3(-8.89,-1.27) 4(-8.89,1.27) 5(-6.35,-1.27) 6(-6.35,1.27) 7(-3.81,-1.27) 8(-3.81,1.27) 9(-1.27,-1.27) 10(-1.27,1.27) 11(1.27,-1.27) 12(1.27,1.27) 13(3.81,-1.27) 14(3.81,1.27) 15(6.35,-1.27) 16(6.35,1.27) 17(8.89,-1.27) 18(8.89,1.27) 19(11.43,-1.27) 20(11.43,1.27)
  silkscreen extent -16.4,-4.7 16.4,4.4, body extent -16.45,-4.39 16.45,4.7, height 9.09
TAG-TC2030-LEGS [mm] "Tag-Connect TC2030 with legs footprint"
  round 2.375 hole 2.375 unplated mask+0: 0(-2.54,-2.54) 0(-2.54,2.54) 0(0.635,-2.54) 0(0.635,2.54)
  round 0.85 hole 1 unplated mask+0: 0(-2.54,0) 0(2.54,-1.016) 0(2.54,1.016)
  round 0.8 smd paste-0.4: 1(-1.27,-0.635) 2(-1.27,0.635) 3(0,-0.635) 4(0,0.635) 5(1.27,-0.635) 6(1.27,0.635)
  Top Layer keep-out lines w0.1: 0.65,0.5 0.65,-0.5 ; -0.65,0.5 -0.65,-0.5 ; 1.3,0 -1.3,0
  Bottom Layer keep-out region: -3.302,4.572 -1.778,4.572 -1.778,3.9 -3.302,3.9
  Bottom Layer keep-out region: -0.127,4.572 1.397,4.572 1.397,3.9 -0.127,3.9
  Bottom Layer keep-out region: -0.127,-3.9 1.397,-3.9 1.397,-4.572 -0.127,-4.572
  Bottom Layer keep-out region: -3.302,-3.9 -1.778,-3.9 -1.778,-4.572 -3.302,-4.572
  silkscreen extent -3.54,-1.8 3.5,1.8
TE_RT1_2COIL_LATCHING [mm] "TE Connectivity/Schrack RT1/RT3 type latching SPST relay"
  round 2 hole 1.3: COM1(-3.75,-7.85) COM2(3.75,-7.85) NO1(-3.75,-13.09) NO2(3.75,-13.09) PLUS(0,12.25) SET(3.75,12.25)
  rect 2x2 hole 1.3: RESET(-3.75,12.25)
  silkscreen extent -6.35,-14.55 6.35,14.55, body extent -6.35,-14.55 6.35,14.55, height 16
TO-263_TRIAC_N [mm] "D2-PAK, 4-Leads, Body 9.2x10.2mm, Pitch 2.54mm, Lead Span 15.4mm, IPC Medium Density"
  rect 3.8x1 smd: COM(-6.3,2.54) G(-6.3,-2.54)
  rect 9.3x10.4 smd: OUT(3.55,0)
  silkscreen extent -6.42,-5.2 -1.5,5.2, body extent -2.95,-5.2 6.4,5.2, height 4.6
TP_TH078H127P [mil] "30mil Trough Hole Test Point"
  round 50 hole 30 mask+0: 1(0,0)
TSOP65P640X120-20N [mm] "TSSOP, 20-Leads, Body 6.50x4.40mm, Pitch 0.65mm, IPC Medium Density"
  rect 1.35x0.4 smd: 1(-2.875,2.925) 2(-2.875,2.275) 3(-2.875,1.625) 4(-2.875,0.975) 5(-2.875,0.325) 6(-2.875,-0.325) 7(-2.875,-0.975) 8(-2.875,-1.625) 9(-2.875,-2.275) 10(-2.875,-2.925) 11(2.875,-2.925) 12(2.875,-2.275) 13(2.875,-1.625) 14(2.875,-0.975) 15(2.875,-0.325) 16(2.875,0.325) 17(2.875,0.975) 18(2.875,1.625) 19(2.875,2.275) 20(2.875,2.925)
  silkscreen extent -3,-3.3 1.85,3.8, body extent -2.25,-3.3 2.25,3.3, height 1.3

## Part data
C1 C123: library part CMP-CAP-00014-5, "Multilayer Ceramic Capacitor, 22 uF, 16 V, ± 20%, X5R, 0805 [2012 Metric]", Case Code (Imperial)=0805, Case Code (Metric)=2012, Dielectric=X5R, Max Operating Temperature=85°C, Min Operating Temperature=-55°C, Package Quantity=1, Tolerance=20%, Voltage=16V
C2: library part CMP-CAP-00028-3, "Film Capacitor, Polypropylene, 1000V, 20% +Tol, 20% -Tol, 0.0022uF, Through Hole Mount", Case/Package=Radial, Dielectric=PP, Max Operating Temperature=110°C, Min Operating Temperature=-40°C, Tolerance=20%, Voltage Rating (DC)=1kV
C3 C4 C12 C15 C16 C25 C120 C121: library part CMP-CAP-00002-13, "Multilayer Ceramic Capacitor, 0.1 uF, 50 V, ± 10%, X7R, 0603 [1608 Metric]", Case Code (Imperial)=0603, Case Code (Metric)=1608, Dielectric=X7R, Max Operating Temperature=125°C, Min Operating Temperature=-55°C, Package Quantity=15000, Tolerance=10%, Voltage=50V
C5: library part CMP-CAP-00013-4, "CAP FILM 600VAC(X1) 0.33 UF 10%", Tolerance=10%, Voltage="600 VAC"
C6 C7 C118: library part CMP-CAP-00006-11, "Multilayer Ceramic Capacitor, 0.033 uF, 50 V, ± 10%, X7R, 0603 [1608 Metric]", Case Code (Imperial)=0603, Case Code (Metric)=1608, Dielectric=X7R, Max Operating Temperature=125°C, Min Operating Temperature=-55°C, Package Quantity=1, Tolerance=10%, Voltage=50V
C8 C9: library part CMP-CAP-00001-13, "Ceramic Capacitor, Multilayer, Ceramic, 25V, 10% +Tol, 10% -Tol, X7R, 15% TC, 1uF, Surface Mount, 0603", Case Code (Imperial)=0603, Case Code (Metric)=1608, Dielectric=X7R, Max Operating Temperature=125°C, Min Operating Temperature=-55°C, Tolerance=10%, Voltage=25V
C119 C122: library part CMP-CAP-00007-11, "Multilayer Ceramic Capacitor, 4.7 uF, 25 V, ± 10%, X5R, 0603 [1608 Metric]", Case Code (Imperial)=0603, Case Code (Metric)=1608, Dielectric=X7R, Max Operating Temperature=85°C, Min Operating Temperature=-55°C, Package Quantity=1, Tolerance=10%, Voltage=25V
C124 C125: library part CMP-CAP-00011-4, "Capacitor; Al Electrolytic; Cap 470 uF; Tol 20%; Vol-Rtg 35 VDC; Radial; 10x17 mm", Case/Package=Radial, Max Operating Temperature=105°C, Min Operating Temperature=-40°C, Tolerance=20%, Voltage Rating (DC)=35V
D1 D2 D3 D4 D5: library part CMP-DIO-00000-5, "Rectifier Diode Switching 100V 0.3A 4ns 2-Pin SOD-123 T/R / DIODE GEN PURP 100V 150MA SOD123", Case/Package=SOD-123-2, Forward Current=150mA, Forward Voltage=1V, Power Dissipation=400mW, Voltage Rating (DC)=100V
D6: library part CMP-DIO-00006-4, "Bridge Rectifier Abs/Sopa-4 T&r 5K Rohs Compliant: Yes", Case/Package=SMD/SMT
D7 D10: library part CMP-DIO-00011-1, "SMAZ10-13 Series 1 W 10 V 200 mA Surface Mount Zener Diode - DO-214AC", Case/Package=SMA, Forward Current=1A, Forward Voltage=1.2V, Power Dissipation=1W
D8 D9: library part CMP-DIO-00003-5, "DIODE ZENER 8.2V 1W SMA", Case/Package=SMA, Forward Current=1A, Forward Voltage=1.2V, Power Dissipation=1W, Voltage Rating (DC)=8.2V
D20: library part CMP-DIO-00001-5, "DIODE SCHOTTKY 30V 1A SOD123 / Rectifier Diode Schottky 30V 1A 2-Pin SOD-123 T/R", Case/Package=SOD-123-2, Forward Current=1A, Forward Voltage=470mV, Power Dissipation=400mW, Voltage Rating (DC)=30V
D22: library part CMP-DIO-00004-5, "SMAJ24A Series 400 W 24 V Surface Mount Uni-Directional TVS Diode - DO-214AC", Case/Package=SMA, Forward Current=1A, Forward Voltage=1.2V, Power Dissipation=400W, Voltage Rating (DC)=24V
D57 D58 D59: library part CMP-DIO-00007-4, "Diode Rectifier 2000V 1A 2-Pin DO-214AC T/R", Case/Package=SMA, Forward Current=1A, Forward Voltage=1V, Power Dissipation=1.4W, Voltage Rating (DC)=2kV
D60: library part CMP-LED-00004-3, "Red 3.2 x 1.6 x 1.05 mm (1206) 120º Water Clear 150 mcd 1.95 V Chip LED Lamp SMT", Case/Package=1206, Color=Red, Forward Current=20mA, Forward Voltage=1.95V, Max Operating Temperature=85°C, Min Operating Temperature=-40°C
GDT1: library part CMP-PROT-00004-3, "CG3 Series - Two Terminal High Voltage Gas Plasma Arresters, 1000V, 10kA, plug in, RoHS", Breakdown Voltage=1.0kV
GDT2: library part CMP-PROT-00003-4, "Arrestor; 2500 V (min.) (breakdown); Rugged Ceramic-metal Package; 1 Pf (max.)", Breakdown Voltage=2.5kV
J1 J2 J3 J4 J5 J6 J7 J8 J9: library part CMP-CONN-00004-5, "Quick Disconnect Terminal 12-24AWG Brass Tab 14.02mm Tin Over Copper/Tin Over Nickel Bag"
J10: library part CMP-CONN-00014-4, "KK 254 Solid Header, Vertical, with Friction Lock, 2 Circuits, Tin (Sn) Plating"
J11: library part CMP-CONN-00034-1, "Conn Shrouded Header (4 Sides) HDR 20 POS 2.54mm Solder ST Top Entry Thru-Hole"
J12: library part CMP-CONN-00033-3, "Headers & Wire Housings High Reliability Header Strips, 0.050 pitch"
J13: library part CMP-CONN-00036-1, "2x3 0.100\" pitch through-hole vertical header shrouded"
J14 J17: library part CMP-CONN-00022-4, "THT Vertical Pin Header WR-PHD, Pitch 2.54 mm, Single Row, 2 pins", Color=Black, Contact Resistance=20mR, Current Rating=3A, Max Operating Temperature=125°C, Min Operating Temperature=-40°C, Operating Supply Voltage=250V
J15: library part CMP-NOBOM-00014-2, "AVX 10-pin PCB edge connector, to connect to the arrow side of the connector."
J16: library part CMP-NOBOM-00015-2, "AVX 10-pin PCB edge connector, to connect to the arrow side of the connector."
K1: library part CMP-RELAY-00000-5, "Electromechanical Relay SPST-NO 16A 12VDC 240Ohm Through Hole", Coil Power=600mW, Contact Current Rating=16A, Contact Voltage Rating (AC)=250V
L2: library part CMP-IND-00005-4, "47 µH Shielded Toroidal Inductor 10.7 A 16mOhm Max Radial, Vertical (Open)", Case/Package=Radial, Current Rating=10.7A, DC Resistance (DCR)=16mR, Max Operating Temperature=105°C, Min Operating Temperature=-55°C, Tolerance=15%
MECH1: library part CMP-LED-00003-7, "Light Pipe, Rigid, Vertical, Board Mount, SMD LED, .400 in., Flat Face"
MECH2: library part CMP-THERM-00003-4, "Heatsink TO-263 19.38X25.40MM"
MH2 MH3 MH4 MH5: library part CMP-NOBOM-00004-3, "Hole for M3 screw, unplated"
NRST_MCU PA0 PA1 PA2 PA3 PA4 PA5 PA6 PA7 PA11 PB6 PC14 PC15 SNS T_ON ZC: library part CMP-NOBOM-00008-2, "Test Point plated unpopulated.  30mil hole dia.  50mil copper dia."
NT1: library part CMP-NOBOM-00011-1, "Net tie with several footprints"
P1: library part CMP-NOBOM-00012-1, "Tag Connect TC2030 with holes for legs"
Q1: library part CMP-BJT-00000-3, "BCV72 Series 60 V 100 mA 250 mW NPN SMT General Purpose Transistor - SOT-23", Case/Package=TO-236-3, Collector Base Voltage (VCBO)=80V, Collector Emitter Voltage (VCEO)=60V, Frequency=100MHz, Max Collector Current=100mA
Q2 Q3 Q5: library part CMP-FET-00000-3, "MOSFET Transistor, N Channel, 3.4 A, 30 V, 0.046 ohm, 4.5 V, 800 mV", Case/Package=SOT-23, Continuous Drain Current (ID)=3.4A, Drain to Source Resistance=46mR, Drain to Source Voltage (Vdss)=30V
Q4: library part CMP-THY-00001-7, "Thyristor AC Switch Triac 700V 126A 3-Pin(2+Tab) D2PAK Tube", Case/Package=D2PAK, Max Repetitive Reverse Voltage (Vrrm)=700V
R1: library part CMP-RES-00078-5, "SMD Chip Resistor, 220 KOhm, ± 1%, 500 mW, 2010 [5025 Metric], Thick Film, High Voltage", Case Code (Imperial)=2010, Case Code (Metric)=5025, Max Operating Temperature=155°C, Max Power Dissipation=500mW, Min Operating Temperature=-55°C, Power Rating=1.0W, Resistor Type="Thick Film", Temperature Coefficient=100ppm/°C, Tolerance=1%, Voltage Rating=3kV
R2 R3 R10: library part CMP-RES-00067-6, "SMD Chip Resistor, 1 MOhm, ± 1%, 1 W, 2512 [6332 Metric], Thick Film, High Voltage", Case Code (Imperial)=2512, Case Code (Metric)=6432, Max Operating Temperature=155°C, Max Power Dissipation=1.0W, Min Operating Temperature=-55°C, Resistor Type="Thick Film", Temperature Coefficient=100ppm/°C, Tolerance=1%, Voltage Rating=3000V
R4 R17 R24 R54: library part CMP-RES-00002-10, "SMD Chip Resistor, 475 kOhm, ± 1%, 100 mW, 0603 [1608 Metric], Thick Film, Precision", Case Code (Imperial)=0603, Case Code (Metric)=1608, Max Operating Temperature=155°C, Max Power Dissipation=100mW, Min Operating Temperature=-55°C, Package Quantity=1, Resistor Type="Thick Film", Temperature Coefficient=100ppm/°C, Tolerance=1%, Voltage Rating=75V
R5 R8 R12 R23 R26 R27 R58: library part CMP-RES-00000-13, "Res Thick Film 0603 1M Ohm 1% 1/10W ±100ppm/°C Molded SMD Punched Carrier T/R", Case Code (Imperial)=0603, Case Code (Metric)=1608, Max Operating Temperature=155°C, Max Power Dissipation=100mW, Min Operating Temperature=-55°C, Package Quantity=1, Resistor Type="Thick Film", Temperature Coefficient=100ppm/°C, Tolerance=1%, Voltage Rating=75V
R6 R39 R47: library part CMP-RES-00064-10, "Res Thin Film 0603 4.22K Ohm 0.1% 1/10W ±25ppm/°C Molded SMD SMD Punched Carrier T/R", Case Code (Imperial)=0603, Case Code (Metric)=1608, Max Operating Temperature=155°C, Max Power Dissipation=100mW, Min Operating Temperature=-55°C, Package Quantity=5000, Ratings=AEC-Q200, Resistor Type="Thin Film", Temperature Coefficient=25ppm/°C, Tolerance=0.1%, Voltage Rating=75V
R7 R9 R29 R30 R35 R50 R59: library part CMP-RES-00004-12, "Resistor Thick Film 0603 100K Ohm 1% 1/10W 100ppm/C Molded SMD Punched Carrier T/R", Case Code (Imperial)=0603, Case Code (Metric)=1608, Max Operating Temperature=155°C, Max Power Dissipation=100mW, Min Operating Temperature=-55°C, Package Quantity=5000, Resistor Type="Thick Film", Temperature Coefficient=100ppm/°C, Tolerance=1%, Voltage Rating=75V
R11: library part CMP-RES-00063-10, "Res Thin Film 0603 17.4K Ohm 0.1% 0.1W(1/10W) ±25ppm/C Pad SMD Automotive T/R", Case Code (Imperial)=0603, Case Code (Metric)=1608, Max Operating Temperature=155°C, Max Power Dissipation=100mW, Min Operating Temperature=-55°C, Package Quantity=5000, Ratings=AEC-Q200, Resistor Type="Thin Film", Temperature Coefficient=25ppm/°C, Tolerance=0.1%, Voltage Rating=75V
R13 R19 R25 R32 R44 R62: library part CMP-RES-00062-10, "Res Thin Film 0603 27.4K Ohm 0.1% 0.1W(1/10W) ±25ppm/C Pad SMD Automotive T/R", Case Code (Imperial)=0603, Case Code (Metric)=1608, Max Operating Temperature=155°C, Max Power Dissipation=100mW, Min Operating Temperature=-55°C, Package Quantity=5000, Ratings=AEC-Q200, Resistor Type="Thin Film", Temperature Coefficient=25ppm/°C, Tolerance=0.1%, Voltage Rating=75V
R14: library part CMP-RES-00079-5, "Res Thick Film 1206 51 Ohm 5% 0.33W ±200ppm/°C Molded SMD Punched Carrier T/R", Case Code (Imperial)=1206, Case Code (Metric)=3216, Max Operating Temperature=155°C, Max Power Dissipation=667mW, Min Operating Temperature=-55°C, Power=660mW, Ratings=AEC-Q200, Temperature Coefficient=200ppm/°C, Tolerance=5%, Voltage Rating=500V
R15: library part CMP-RES-00060-10, "Res Thick Film 0603 140K Ohm 1% 1/10W ±100ppm/°C Molded SMD SMD Paper T/R", Case Code (Imperial)=0603, Case Code (Metric)=1608, Max Operating Temperature=155°C, Max Power Dissipation=100mW, Min Operating Temperature=-55°C, Resistor Type="Thick Film", Temperature Coefficient=100ppm/°C, Tolerance=1%, Voltage Rating=75V
R16 R18: library part CMP-RES-00016-12, "Res Thick Film 0603 10K Ohm 1% 1/10W ±100ppm/°C Molded SMD SMD Paper T/R", Case Code (Imperial)=0603, Case Code (Metric)=1608, Max Operating Temperature=155°C, Max Power Dissipation=100mW, Min Operating Temperature=-55°C, Ratings=AEC-Q200, Resistor Type="Thick Film", Temperature Coefficient=100ppm/°C, Tolerance=1%, Voltage Rating=75V
R20: library part CMP-RES-00061-10, "Res Thick Film 0603 2.74K Ohm 1% 1/10W ±100ppm/°C Molded SMD SMD Paper T/R", Case Code (Imperial)=0603, Case Code (Metric)=1608, Max Operating Temperature=155°C, Max Power Dissipation=100mW, Min Operating Temperature=-55°C, Resistor Type="Thick Film", Temperature Coefficient=100ppm/°C, Tolerance=1%, Voltage Rating=75V
R21: library part CMP-RES-00012-10, "SMD Chip Resistor, 221 Ohm, ± 1%, 100 mW, 0603 [1608 Metric], Thick Film, Precision", Case Code (Imperial)=0603, Case Code (Metric)=1608, Max Operating Temperature=155°C, Max Power Dissipation=100mW, Min Operating Temperature=-55°C, Package Quantity=1, Resistor Type="Thick Film", Temperature Coefficient=100ppm/°C, Tolerance=1%, Voltage Rating=75V
R22: library part CMP-RES-00080-5, "Res Thick Film 1206 150 Ohm 5% 1/3W ±200ppm/°C Molded SMD SMD Punched Carrier T/R", Case Code (Imperial)=1206, Case Code (Metric)=3216, Max Operating Temperature=155°C, Max Power Dissipation=667mW, Min Operating Temperature=-55°C, Power=660mW, Ratings=AEC-Q200, Temperature Coefficient=200ppm/°C, Tolerance=5%, Voltage Rating=500V
R28: library part CMP-RES-00008-10, "Res Thick Film 0603 33.2K Ohm 1% 1/10W +/-100ppm/ßC Molded SMD Punched Carrier T/R", Case Code (Imperial)=0603, Case Code (Metric)=1608, Max Operating Temperature=155°C, Max Power Dissipation=100mW, Min Operating Temperature=-55°C, Resistor Type="Thick Film", Temperature Coefficient=100ppm/°C, Tolerance=1%, Voltage Rating=50V
R31 R64: library part CMP-RES-00066-10, "Res Thin Film 0603 6.2K Ohm 0.1% 1/10W ±25ppm/°C Molded SMD SMD Punched Carrier T/R", Case Code (Imperial)=0603, Case Code (Metric)=1608, Max Operating Temperature=155°C, Max Power Dissipation=100mW, Min Operating Temperature=-55°C, Package Quantity=1, Ratings=AEC-Q200, Resistor Type="Thin Film", Temperature Coefficient=25ppm/°C, Tolerance=0.1%, Voltage Rating=75V
R33 R34: library part CMP-RES-00081-7, "SMD Chip Resistor, 392 Ohm, 1%, 100 mW, 0603 [1608 Metric], Thick Film, Precision", Case Code (Imperial)=0603, Case Code (Metric)=1608, Max Operating Temperature=155°C, Max Power Dissipation=100mW, Min Operating Temperature=-55°C, Package Quantity=1, Resistor Type="Thick Film", Temperature Coefficient=100ppm/°C, Tolerance=1%, Voltage Rating=75V, Voltage Rating (DC)=50V
R36 R37: library part CMP-RES-00082-7, "Res Thin Film 0603 1M Ohm 0.1% 0.1W(1/10W) ±25ppm/C Pad SMD T/R", Case Code (Imperial)=0603, Case Code (Metric)=1608, Max Operating Temperature=155°C, Max Power Dissipation=100mW, Min Operating Temperature=-55°C, Package Quantity=5000, Ratings=AEC-Q200, Resistor Type="Thin Film", Temperature Coefficient=25ppm/°C, Tolerance=0.1%, Voltage Rating=75V
R48 R49 R52 R56: library part CMP-009-00190-11, "Res Thick Film 0603 1K Ohm 1% 1/10W ±100ppm/°C Molded SMD Punched Carrier T/R", Case Code (Imperial)=0603, Case Code (Metric)=1608, Max Operating Temperature=155°C, Max Power Dissipation=100mW, Min Operating Temperature=-55°C, Resistor Type="Thick Film", Temperature Coefficient=100ppm/°C, Tolerance=1%, Voltage Rating=75V
R181: library part CMP-RES-00069-5, "SMD Chip Resistor, 100 Ohm, ± 1%, 500 mW, 0805 [2012 Metric], Thick Film, Anti-Surge", Case Code (Imperial)=0805, Case Code (Metric)=2012, Max Operating Temperature=155°C, Max Power Dissipation=500mW, Min Operating Temperature=-55°C, Ratings=AEC-Q200, Temperature Coefficient=100ppm/°C, Tolerance=1%, Voltage Rating=150V
RV1 RV2 RV3 RV4: library part CMP-PROT-00005-4, "Thermally Protected Varistor 300 V RMS 775 V Clamp 10000 A 800 pF Radial Lead", Varistor Voltage=517V, Voltage Rating (AC)=300V
SJ1: library part CMP-NOBOM-00017-1, "Jumper that needs hand solder to close it."
TP9 TP12 TP13 TP15 TP16: library part NOBOM-00007, "Test point, TH, 0.78mm (30mil) hole, 1.27mm (50 mil) pad", Manufacturer="New Horizons"
U1: library part CMP-ICANA-00000-3, "Quad low-power industrial grade standard comparator 14-SOIC -40 to 85", Case/Package=SOIC, Max Supply Voltage=30V, Min Supply Voltage=3V
U2: library part CMP-ICPWR-00000-3, "V-Ref Adjustable 1.24V to 24V 100mA 3-Pin SOT-23 T/R", Case/Package=SOT-23-3, Max Supply Voltage=25V, Tolerance=0.25%
U3: library part CMP-ICANA-00001-3, "Micropower CMOS dual voltage comparator, 9µA, 16V, -40, 0 to 125, 70°C, SO-8, Tape and Reel", Case/Package=SOIC, Max Supply Voltage=16V, Min Supply Voltage=2.7V
U4 U8: library part CMP-ICANA-00002-4, "Op Amp Single Low Power Amplifier R-R I/O ±8V/16V 5-Pin SOT-23 T/R", Case/Package=SOT-23-5, Max Supply Voltage=16V, Min Supply Voltage=2.5V
U5: library part CMP-OPTO-00002-3, "OPTOISOLATOR 5KV TRIAC 6SMD", Case/Package=SMD/SMT
U6: library part CMP-OPTO-00000-5, "Optocoupler Ac-In 1-Ch Transistor Dc-Out 4-Pin Pdip Smd T/R", Case/Package=SMD/SMT
U7: library part CMP-MCU-00001-1, "MCU 32-Bit STM32 ARM Cortex-M0+ RISC 32KB Flash 2V to 3.6V 20-Pin TSSOP T/R"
